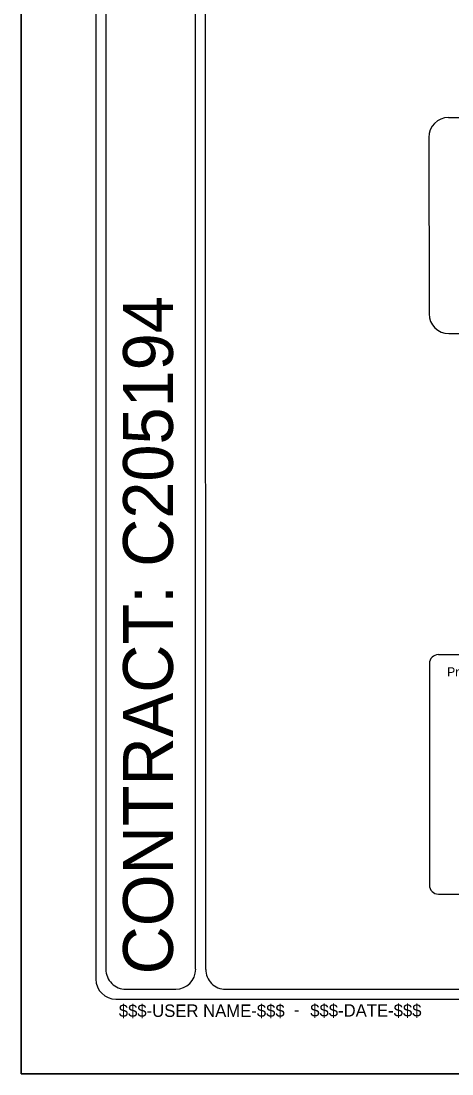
# Model space of a CAD drawing. Extents: x 1359317 to 1361345, y 1001522 to 1002524.
# Drawn here: x 1359316.7 to 1359513.4, y 1001521.9 to 1002002.6 of the extents above; entities that cross this region are included whole.
import ezdxf

# ---------------------------------------------------------------- set-up
doc = ezdxf.new("R2010")
doc.units = 0
for name, color, linetype in [('Sheet Plot Border Outside CELL', 7, 'Continuous'), ('Sheet Title CELL', 7, 'Continuous'), ('Sheet_Data_Field_CELL', 7, 'Continuous'), ('Sheet_Plan_CELL', 7, 'Continuous'), ('Sheet_Title_CELL', 7, 'Continuous'), ('z - Construction', 7, 'Continuous')]:
    doc.layers.add(name, color=color, linetype=linetype)

msp = doc.modelspace()

# ---------------------------------------------------------------- linework, layer by layer
at = {"layer": 'Sheet Plot Border Outside CELL'}
msp.add_lwpolyline([(1359316.74, 1002523.7), (1360865.01, 1002523.7), (1360865.01, 1001521.88), (1359316.74, 1001521.88)], close=True, dxfattribs=at)
at = {"layer": 'Sheet Title CELL'}
for p, q in [((1359507.26, 1001713.32), (1359804.97, 1001713.32)), ((1359503.08, 1001709.14), (1359503.08, 1001608.15)), ((1359507.26, 1001603.97), (1359804.97, 1001603.97))]:
    msp.add_line(p, q, dxfattribs=at)
for centre, start, end in [((1359507.26, 1001709.14), 90, 180), ((1359507.26, 1001608.15), 180, 270)]:
    msp.add_arc(centre, 4.18, start, end, dxfattribs=at)
at = {"layer": 'Sheet_Data_Field_CELL'}
msp.add_line((1359316.74, 1001521.88), (1359316.74, 1001521.88), dxfattribs=at)
at = {"layer": 'Sheet_Title_CELL'}
for p, q in [((1359350.9, 1002480.44), (1359350.9, 1001565.14)), ((1359355.46, 1002475.83), (1359355.45, 1001569.64)), ((1359396.43, 1001569.64), (1359396.43, 1002475.83)), ((1359401, 1001569.63), (1359400.99, 1002475.82)), ((1359511.88, 1001958.52), (1359637.69, 1001958.52)), ((1359502.79, 1001949.43), (1359502.96, 1001868.91)), ((1359512.05, 1001859.86), (1360031.96, 1001859.82)), ((1359409.65, 1001560.53), (1360817.19, 1001560.53)), ((1359360, 1001556.03), (1360821.75, 1001556.03))]:
    msp.add_line(p, q, dxfattribs=at)
msp.add_lwpolyline([(1359364.56, 1001560.53), (1359387.33, 1001560.53)], dxfattribs=at)
for centre, radius, start, end in [((1359511.88, 1001949.43), 9.09, 90, 180), ((1359512.05, 1001868.95), 9.09, 180, 270), ((1359364.56, 1001569.64), 9.11, 179.9993, 270), ((1359387.33, 1001569.68), 9.11, 270, 360), ((1359410.11, 1001569.63), 9.11, 180.0045, 270.0046), ((1359360, 1001565.14), 9.11, 180, 270)]:
    msp.add_arc(centre, radius, start, end, dxfattribs=at)
at = {"layer": 'z - Construction'}
for p, q in [((1359316.74, 1002523.7), (1359316.74, 1001521.88)), ((1359316.74, 1001521.88), (1360865.01, 1001521.88))]:
    msp.add_line(p, q, dxfattribs=at)

# ---------------------------------------------------------------- texts
at = {"layer": 'Sheet Title CELL'}
msp.add_text('Prepared in the Office of:', height=4.1714, rotation=360, dxfattribs=at).set_placement((1359511.17, 1001703.35))
at = {"layer": 'Sheet_Plan_CELL'}
for s, height, p in [('$$$-USER NAME-$$$', 5.6922, (1359361.34, 1001547.91)), ('$$$-DATE-$$$', 5.6922, (1359448.72, 1001548.04)), ('-', 5.69, (1359441.24, 1001548.45))]:
    msp.add_text(s, height=height, dxfattribs=at).set_placement(p)
at = {"layer": 'Sheet_Title_CELL'}
msp.add_text('CONTRACT: C205194', height=22.7686, rotation=90, dxfattribs=at).set_placement((1359386.06, 1001567.33))

doc.saveas('drawing.dxf')
